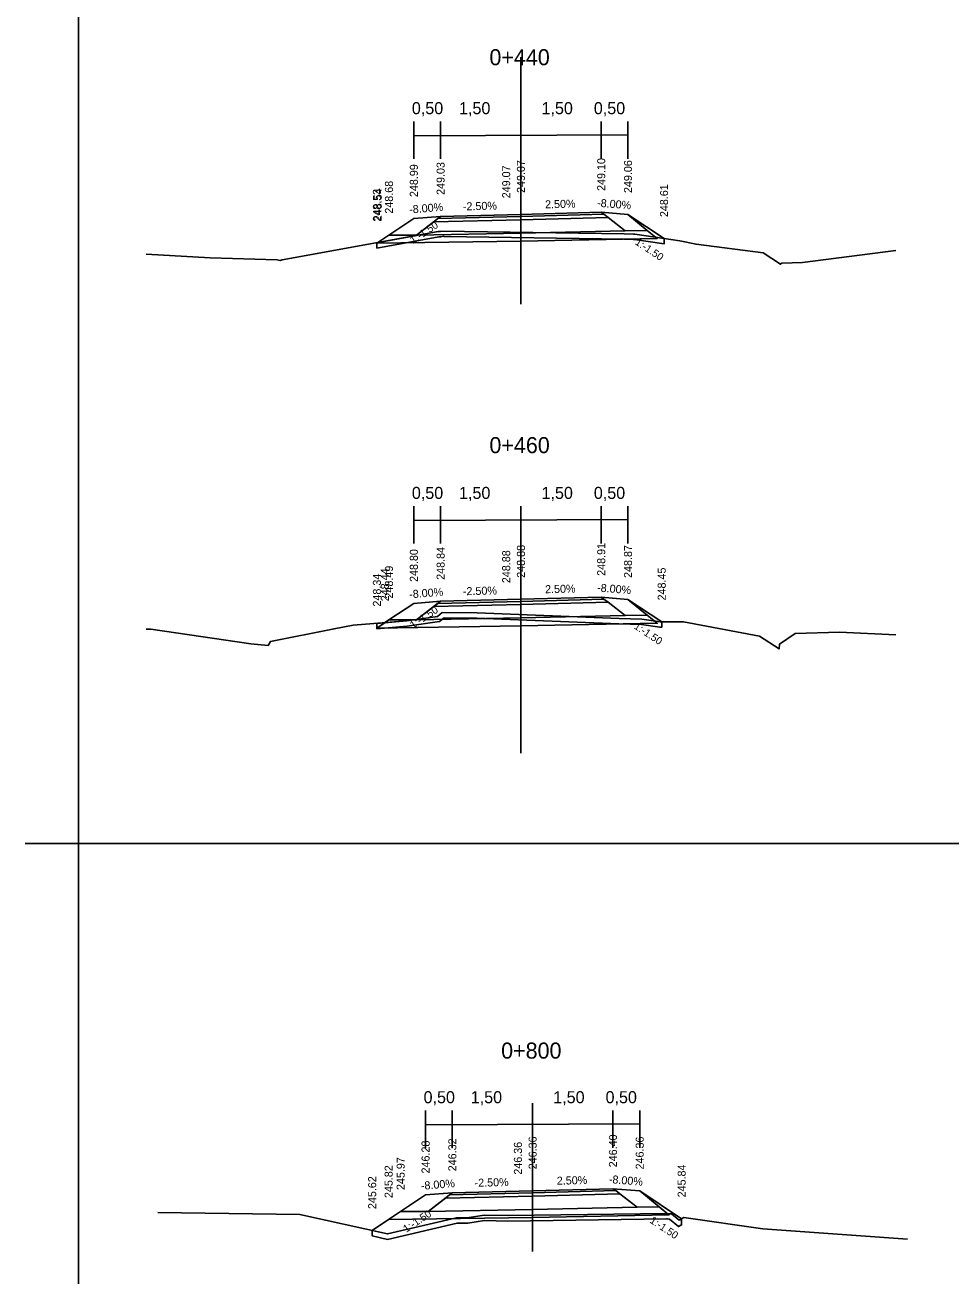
# Model space of a CAD drawing. Extents: x -552501 to -552394, y -1029983 to -1029892.
# Drawn here: x -552500.76 to -552483.46, y -1029960.83 to -1029937.46 of the extents above; entities that cross this region are included whole.
import ezdxf

# ---------------------------------------------------------------- set-up
doc = ezdxf.new("R2010")
doc.units = 0
for name, color, linetype in [('1', 7, 'Continuous'), ('16', 7, 'Continuous'), ('60', 7, 'Continuous'), ('9', 7, 'Continuous'), ('FORMATY', 7, 'Continuous'), ('Implicitní', 7, 'Continuous'), ('rámeček', 7, 'Continuous')]:
    doc.layers.add(name, color=color, linetype=linetype)

msp = doc.modelspace()

# ---------------------------------------------------------------- linework, layer by layer
for points in [[(-552494.183, -1029941.538), (-552494.167, -1029941.528), (-552493.958, -1029941.388), (-552493.493, -1029941.078), (-552492.993, -1029941.038), (-552491.493, -1029941.001), (-552489.993, -1029940.963), (-552489.493, -1029941.003), (-552488.82, -1029941.452)], [(-552498.493, -1029941.746), (-552497.296, -1029941.812), (-552496.048, -1029941.853), (-552495.997, -1029941.861), (-552495.988, -1029941.862), (-552495.987, -1029941.86), (-552495.954, -1029941.853), (-552493.041, -1029941.323), (-552492.998, -1029941.319), (-552492.973, -1029941.315), (-552492.969, -1029941.312), (-552489.565, -1029941.362), (-552489.391, -1029941.369), (-552489.363, -1029941.37), (-552488.522, -1029941.497), (-552488.222, -1029941.558), (-552486.966, -1029941.72), (-552486.643, -1029941.932), (-552486.642, -1029941.925), (-552486.62, -1029941.91), (-552486.236, -1029941.899), (-552484.493, -1029941.679)], [(-552494.183, -1029948.727), (-552494.035, -1029948.628), (-552493.958, -1029948.577), (-552493.493, -1029948.267), (-552492.993, -1029948.227), (-552491.493, -1029948.189), (-552489.993, -1029948.152), (-552489.493, -1029948.192), (-552488.863, -1029948.612)], [(-552498.493, -1029948.747), (-552498.403, -1029948.75), (-552496.537, -1029949.025), (-552496.211, -1029949.051), (-552496.169, -1029948.979), (-552494.982, -1029948.742), (-552494.624, -1029948.677), (-552493.626, -1029948.594), (-552493.054, -1029948.512), (-552492.961, -1029948.437), (-552492.312, -1029948.446), (-552489.66, -1029948.55), (-552489.233, -1029948.56), (-552488.889, -1029948.612), (-552488.458, -1029948.61), (-552487.034, -1029948.88), (-552486.67, -1029949.118), (-552486.66, -1029949.028), (-552486.373, -1029948.83), (-552485.544, -1029948.806), (-552484.493, -1029948.854)], [(-552494.271, -1029959.98), (-552493.964, -1029959.775), (-552493.739, -1029959.625), (-552493.274, -1029959.315), (-552492.774, -1029959.275), (-552491.274, -1029959.238), (-552489.774, -1029959.2), (-552489.274, -1029959.24), (-552488.491, -1029959.762)], [(-552498.274, -1029959.645), (-552495.625, -1029959.679), (-552493.984, -1029960.043), (-552492.698, -1029959.743), (-552492.495, -1029959.742), (-552492.177, -1029959.695), (-552491.739, -1029959.703), (-552488.769, -1029959.664), (-552488.748, -1029959.666), (-552488.679, -1029959.668), (-552488.536, -1029959.787), (-552488.449, -1029959.738), (-552486.975, -1029959.952), (-552484.274, -1029960.14)]]:
    msp.add_lwpolyline(points)
for points in [[(-552492.993, -1029941.038), (-552493.493, -1029941.078), (-552493.958, -1029941.388), (-552493.444, -1029941.388)], [(-552493.444, -1029941.388), (-552493.122, -1029941.138), (-552491.494, -1029941.101), (-552489.865, -1029941.057), (-552489.543, -1029941.307), (-552491.494, -1029941.351)], [(-552491.494, -1029941.041), (-552493.044, -1029941.078), (-552493.122, -1029941.138), (-552491.494, -1029941.101), (-552489.865, -1029941.057), (-552489.942, -1029940.997), (-552491.494, -1029941.041), (-552489.942, -1029940.997), (-552489.993, -1029940.963), (-552491.493, -1029941.001), (-552492.993, -1029941.038), (-552493.044, -1029941.078)], [(-552493.122, -1029941.138), (-552493.044, -1029941.078), (-552491.494, -1029941.041), (-552489.942, -1029940.997), (-552489.865, -1029941.057), (-552491.494, -1029941.101)], [(-552489.993, -1029940.963), (-552489.493, -1029941.003), (-552489.132, -1029941.301), (-552489.543, -1029941.307), (-552489.865, -1029941.057), (-552489.942, -1029940.997)], [(-552494.183, -1029941.538), (-552493.958, -1029941.388), (-552493.444, -1029941.388), (-552491.494, -1029941.351), (-552489.543, -1029941.307), (-552489.132, -1029941.301), (-552488.947, -1029941.451), (-552491.494, -1029941.501)], [(-552494.183, -1029941.531), (-552493.041, -1029941.323), (-552492.998, -1029941.319), (-552492.973, -1029941.315), (-552492.969, -1029941.312), (-552489.565, -1029941.362), (-552489.391, -1029941.369), (-552489.363, -1029941.37), (-552488.82, -1029941.452), (-552488.82, -1029941.553), (-552489.372, -1029941.469), (-552489.394, -1029941.469), (-552489.567, -1029941.462), (-552492.934, -1029941.413), (-552492.931, -1029941.41), (-552492.987, -1029941.418), (-552493.028, -1029941.422), (-552494.183, -1029941.632)], [(-552492.993, -1029948.227), (-552493.493, -1029948.267), (-552493.958, -1029948.577), (-552493.444, -1029948.577)], [(-552493.444, -1029948.577), (-552493.122, -1029948.327), (-552491.494, -1029948.289), (-552489.865, -1029948.246), (-552489.543, -1029948.496), (-552491.494, -1029948.539)], [(-552491.494, -1029948.229), (-552493.044, -1029948.267), (-552493.122, -1029948.327), (-552491.494, -1029948.289), (-552489.865, -1029948.246), (-552489.942, -1029948.186), (-552491.494, -1029948.229), (-552489.942, -1029948.186), (-552489.993, -1029948.152), (-552491.493, -1029948.189), (-552492.993, -1029948.227), (-552493.044, -1029948.267)], [(-552493.122, -1029948.327), (-552493.044, -1029948.267), (-552491.494, -1029948.229), (-552489.942, -1029948.186), (-552489.865, -1029948.246), (-552491.494, -1029948.289)], [(-552489.993, -1029948.152), (-552489.493, -1029948.192), (-552489.132, -1029948.489), (-552489.543, -1029948.496), (-552489.865, -1029948.246), (-552489.942, -1029948.186)], [(-552494.183, -1029948.64), (-552493.626, -1029948.594), (-552493.054, -1029948.512), (-552492.961, -1029948.437), (-552492.312, -1029948.446), (-552489.66, -1029948.55), (-552489.233, -1029948.56), (-552488.889, -1029948.612), (-552488.863, -1029948.612), (-552488.863, -1029948.712), (-552488.896, -1029948.712), (-552489.242, -1029948.66), (-552489.663, -1029948.65), (-552492.315, -1029948.546), (-552492.926, -1029948.537), (-552493.012, -1029948.607), (-552493.615, -1029948.694), (-552494.183, -1029948.741)], [(-552494.183, -1029948.727), (-552493.958, -1029948.577), (-552493.444, -1029948.577), (-552491.494, -1029948.539), (-552489.543, -1029948.496), (-552489.132, -1029948.489), (-552488.947, -1029948.639), (-552491.494, -1029948.689)], [(-552492.774, -1029959.275), (-552493.274, -1029959.315), (-552493.739, -1029959.625), (-552493.225, -1029959.625)], [(-552493.225, -1029959.625), (-552492.903, -1029959.375), (-552491.275, -1029959.338), (-552489.646, -1029959.294), (-552489.324, -1029959.544), (-552491.275, -1029959.588)], [(-552491.275, -1029959.278), (-552492.825, -1029959.315), (-552492.903, -1029959.375), (-552491.275, -1029959.338), (-552489.646, -1029959.294), (-552489.723, -1029959.234), (-552491.275, -1029959.278), (-552489.723, -1029959.234), (-552489.774, -1029959.2), (-552491.274, -1029959.238), (-552492.774, -1029959.275), (-552492.825, -1029959.315)], [(-552492.903, -1029959.375), (-552492.825, -1029959.315), (-552491.275, -1029959.278), (-552489.723, -1029959.234), (-552489.646, -1029959.294), (-552491.275, -1029959.338)], [(-552489.774, -1029959.2), (-552489.274, -1029959.24), (-552488.913, -1029959.538), (-552489.324, -1029959.544), (-552489.646, -1029959.294), (-552489.723, -1029959.234)], [(-552493.964, -1029959.775), (-552493.739, -1029959.625), (-552493.225, -1029959.625), (-552491.275, -1029959.588), (-552489.324, -1029959.544), (-552488.913, -1029959.538), (-552488.728, -1029959.688), (-552491.275, -1029959.738)], [(-552494.271, -1029959.98), (-552493.984, -1029960.043), (-552492.698, -1029959.743), (-552492.495, -1029959.742), (-552492.177, -1029959.695), (-552491.739, -1029959.703), (-552488.769, -1029959.664), (-552488.748, -1029959.666), (-552488.679, -1029959.668), (-552488.536, -1029959.787), (-552488.491, -1029959.762), (-552488.491, -1029959.877), (-552488.547, -1029959.908), (-552488.717, -1029959.767), (-552488.754, -1029959.765), (-552488.772, -1029959.764), (-552491.739, -1029959.803), (-552492.171, -1029959.795), (-552492.487, -1029959.842), (-552492.686, -1029959.843), (-552493.983, -1029960.146), (-552494.271, -1029960.082)]]:
    msp.add_lwpolyline(points, close=True)
at = {"layer": '60'}
for p, q in [((-552491.493, -1029938.066), (-552491.493, -1029942.681)), ((-552491.493, -1029947.066), (-552491.493, -1029951.066)), ((-552491.274, -1029957.6), (-552491.274, -1029960.37))]:
    msp.add_line(p, q, dxfattribs=at)
at = {"layer": '9'}
for p, q in [((-552493.493, -1029939.265), (-552493.493, -1029939.963)), ((-552492.993, -1029939.265), (-552492.993, -1029939.963)), ((-552491.493, -1029939.265), (-552491.493, -1029940.765)), ((-552489.993, -1029939.265), (-552489.993, -1029939.963)), ((-552489.493, -1029939.265), (-552489.493, -1029939.963)), ((-552493.493, -1029946.451), (-552493.493, -1029947.149)), ((-552492.993, -1029946.451), (-552492.993, -1029947.149)), ((-552491.493, -1029946.451), (-552491.493, -1029947.951)), ((-552489.993, -1029946.451), (-552489.993, -1029947.149)), ((-552489.493, -1029946.451), (-552489.493, -1029947.149)), ((-552493.274, -1029957.738), (-552493.274, -1029958.435)), ((-552492.774, -1029957.738), (-552492.774, -1029958.435)), ((-552491.274, -1029957.738), (-552491.274, -1029959.238)), ((-552489.774, -1029957.738), (-552489.774, -1029958.435)), ((-552489.274, -1029957.738), (-552489.274, -1029958.435))]:
    msp.add_line(p, q, dxfattribs=at)
at = {"layer": 'FORMATY'}
for p, q in [((-552499.755, -1029951.75), (-552499.755, -1029953.75)), ((-552500.755, -1029952.75), (-552498.755, -1029952.75))]:
    msp.add_line(p, q, dxfattribs=at)
at = {"layer": 'Implicitní'}
for p, q in [((-552493.483, -1029939.533), (-552489.493, -1029939.515)), ((-552493.483, -1029946.719), (-552489.493, -1029946.701)), ((-552493.264, -1029958.005), (-552489.274, -1029957.988))]:
    msp.add_line(p, q, dxfattribs=at)
at = {"layer": 'rámeček'}
for p, q in [((-552499.755, -1029952.75), (-552499.755, -1029923.05)), ((-552499.755, -1029952.25), (-552499.755, -1029952.75)), ((-552499.755, -1029952.75), (-552394.755, -1029952.75)), ((-552499.755, -1029952.75), (-552394.755, -1029952.75)), ((-552499.755, -1029952.75), (-552394.755, -1029952.75)), ((-552499.755, -1029982.45), (-552499.755, -1029952.75))]:
    msp.add_line(p, q, dxfattribs=at)

# ---------------------------------------------------------------- texts
for rotation, p in [(33.6902, (-552493.509, -1029941.558)), (326.3098, (-552489.373, -1029941.552)), (33.6902, (-552493.509, -1029948.746)), (326.3098, (-552489.394, -1029948.727)), (33.6905, (-552493.635, -1029960.025)), (326.3098, (-552489.099, -1029959.825))]:
    msp.add_text('1:-1.50', height=0.14, rotation=rotation).set_placement(p)
at = {"layer": '1'}
for s, p in [('0+440', (-552492.081, -1029938.216)), ('0+460', (-552492.081, -1029945.461)), ('0+800', (-552491.862, -1029956.77))]:
    msp.add_text(s, height=0.3, dxfattribs=at).set_placement(p)
at = {"layer": '16'}
for s, p in [('0,50', (-552493.53, -1029939.13)), ('1,50', (-552492.649, -1029939.13)), ('1,50', (-552491.108, -1029939.13)), ('0,50', (-552490.131, -1029939.13)), ('0,50', (-552493.53, -1029946.316)), ('1,50', (-552492.649, -1029946.316)), ('1,50', (-552491.108, -1029946.316)), ('0,50', (-552490.131, -1029946.316)), ('0,50', (-552493.311, -1029957.603)), ('1,50', (-552492.43, -1029957.603)), ('1,50', (-552490.889, -1029957.603)), ('0,50', (-552489.912, -1029957.603))]:
    msp.add_text(s, height=0.225, dxfattribs=at).set_placement(p)
for s, rotation, p in [('248.99', 90, (-552493.418, -1029940.678)), ('249.03', 90, (-552492.918, -1029940.638)), ('249.07', 90, (-552491.693, -1029940.701)), ('249.07', 90, (-552491.418, -1029940.601)), ('249.10', 90, (-552489.918, -1029940.563)), ('249.06', 90, (-552489.418, -1029940.603)), ('248.68', 90, (-552493.883, -1029940.988)), ('248.53', 90, (-552494.108, -1029941.138)), ('248.54', 90, (-552494.092, -1029941.128)), ('248.61', 90, (-552488.745, -1029941.052)), ('-8.00%', 4.5739, (-552493.574, -1029940.985)), ('-2.50%', 1.4321, (-552492.575, -1029940.928)), ('2.50%', 1.4321, (-552491.04, -1029940.889)), ('-8.00%', 355.4261, (-552490.074, -1029940.857)), ('248.88', 90, (-552491.418, -1029947.789)), ('248.91', 90, (-552489.918, -1029947.752)), ('248.87', 90, (-552489.418, -1029947.792)), ('248.80', 90, (-552493.418, -1029947.867)), ('248.84', 90, (-552492.918, -1029947.827)), ('248.88', 90, (-552491.693, -1029947.889)), ('248.44', 90, (-552493.96, -1029948.228)), ('248.49', 90, (-552493.883, -1029948.177)), ('248.45', 90, (-552488.788, -1029948.212)), ('248.34', 90, (-552494.108, -1029948.327)), ('-8.00%', 4.5739, (-552493.574, -1029948.173)), ('-2.50%', 1.4321, (-552492.575, -1029948.116)), ('2.50%', 1.4321, (-552491.04, -1029948.078)), ('-8.00%', 355.4261, (-552490.074, -1029948.045)), ('246.28', 90, (-552493.199, -1029958.915)), ('246.32', 90, (-552492.699, -1029958.875)), ('246.36', 90, (-552491.474, -1029958.938)), ('246.36', 90, (-552491.199, -1029958.838)), ('246.40', 90, (-552489.699, -1029958.8)), ('246.36', 90, (-552489.199, -1029958.84)), ('245.97', 90, (-552493.664, -1029959.225)), ('245.82', 90, (-552493.889, -1029959.375)), ('245.84', 90, (-552488.416, -1029959.362)), ('245.62', 90, (-552494.196, -1029959.58)), ('-8.00%', 4.5739, (-552493.355, -1029959.221)), ('-2.50%', 1.4321, (-552492.356, -1029959.165)), ('2.50%', 1.4321, (-552490.821, -1029959.126)), ('-8.00%', 355.4261, (-552489.855, -1029959.094))]:
    msp.add_text(s, height=0.15, rotation=rotation, dxfattribs=at).set_placement(p)

doc.saveas('drawing.dxf')
